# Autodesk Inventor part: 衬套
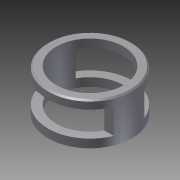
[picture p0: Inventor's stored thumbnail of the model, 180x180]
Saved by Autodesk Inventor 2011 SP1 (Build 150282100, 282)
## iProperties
Created: 2013-12
Part Number: 衬套
Document SubType Name: Modeling
Designer: Administrator
Density: 1 g/cm^3
Author: Administrator
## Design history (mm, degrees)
sketch "草图1"
  geometry: C1 r 30 at (0, 0); C2 r 24 at (0, 0); 1 further point
  constraints: 2 centre point, 2 coincident
  dimensions: "d0" = 60 diameter of C1; "d1" = 48 diameter of C2
extrude "拉伸1" new body sketch "草图1" distance "d2" = 30; taper "d3" = 0 deg
node "工作平面1"
sketch "草图2"
  geometry: L1 (-30, 30)-(30, 30) reference; L2 (-30, 0)-(30, 0) reference; L3 (30, 0)-(30, 30) reference; L4 (-30, 0)-(-30, 30) reference; L5 (11, 24)-(45.044, 24); L6 (45.044, 24)-(45.044, 6); L7 (45.044, 6)-(11, 6); L8 (11, 6)-(11, 24); 3 further points
  constraints: 8 end point, 2 parallel, 1 horizontal, 1 horizontal alignment, 1 midpoint, 1 perpendicular
  dimensions: "d5" = 15 distance of point (0, 0) point (0, 15); "d6" = 18 distance of L7.end L5.start; "d7" = 11 distance of point (11, 15) point (0, 15)
extrude "拉伸2" cut sketch "草图2" distance "d8" = 70; taper "d9" = 0 deg
mirror "镜像1"
chamfer "倒角1" distance "d10" = 1; stored, may be unused: second distance "d11" = 2, angle "d12" = 45 deg
node "实体1"
node "投影回路1"
